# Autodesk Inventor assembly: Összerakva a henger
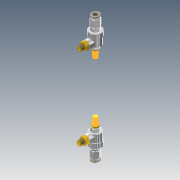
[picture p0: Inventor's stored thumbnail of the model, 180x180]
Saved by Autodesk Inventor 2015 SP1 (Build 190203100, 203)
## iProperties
Created: 2012-12
Part Number: Összerakva a henger
Document SubType Name: Assembly
Designer: Marci
Author: Marci
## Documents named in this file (5)
- C:\Users\TREINA11\Desktop\#01- Polymechanics and Automation\01 - 3D Models\Pneumatic System\Összerakva a henger.iam
- C:\Users\TREINA11\Desktop\#01- Polymechanics and Automation\01 - 3D Models\Pneumatic System\Hollanderes közcsavar.ipt
- C:\Users\TREINA11\Desktop\#01- Polymechanics and Automation\01 - 3D Models\Pneumatic System\Gyorsleeresztő szelep.ipt
- C:\Users\TREINA11\Desktop\#01- Polymechanics and Automation\01 - 3D Models\Pneumatic System\Hangtompító.ipt
- C:\Users\TREINA11\Desktop\#01- Polymechanics and Automation\01 - 3D Models\Pneumatic System\1.4 12 gyorscsat.ipt
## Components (8 placed, 4 different names)
1. Hollanderes közcsavar:1 — Mate:13, Mate:14
2. Hollanderes közcsavar:2 — Mate:11, Mate:12
3. Gyorsleeresztő szelep:1 — Mate:11, Mate:12, Flush:1, Mate:16, Mate:17, Mate:20, Mate:21
4. Gyorsleeresztő szelep:2 — Mate:13, Mate:14, Flush:2, Mate:18, Mate:19, Mate:22, Mate:23
5. Hangtompító:1 — Mate:16, Mate:17
6. Hangtompító:2 — Mate:18, Mate:19
7. 1.4 12 gyorscsat:1 — Mate:20, Mate:21
8. 1.4 12 gyorscsat:2 — Mate:22, Mate:23
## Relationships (14: Mate 12, Flush 2)
- Mate:11: Hollanderes közcsavar:2 ↔ Gyorsleeresztő szelep:1
- Mate:12: Hollanderes közcsavar:2 ↔ Gyorsleeresztő szelep:1
- Mate:13: Hollanderes közcsavar:1 ↔ Gyorsleeresztő szelep:2
- Mate:14: Hollanderes közcsavar:1 ↔ Gyorsleeresztő szelep:2
- Flush:1: Gyorsleeresztő szelep:1
- Flush:2: Gyorsleeresztő szelep:2
- Mate:16: Gyorsleeresztő szelep:1 ↔ Hangtompító:1
- Mate:17: Gyorsleeresztő szelep:1 ↔ Hangtompító:1
- Mate:18: Gyorsleeresztő szelep:2 ↔ Hangtompító:2
- Mate:19: Gyorsleeresztő szelep:2 ↔ Hangtompító:2
- Mate:20: Gyorsleeresztő szelep:1 ↔ 1.4 12 gyorscsat:1
- Mate:21: Gyorsleeresztő szelep:1 ↔ 1.4 12 gyorscsat:1
- Mate:22: Gyorsleeresztő szelep:2 ↔ 1.4 12 gyorscsat:2
- Mate:23: Gyorsleeresztő szelep:2 ↔ 1.4 12 gyorscsat:2
